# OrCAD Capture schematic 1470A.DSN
size Custom
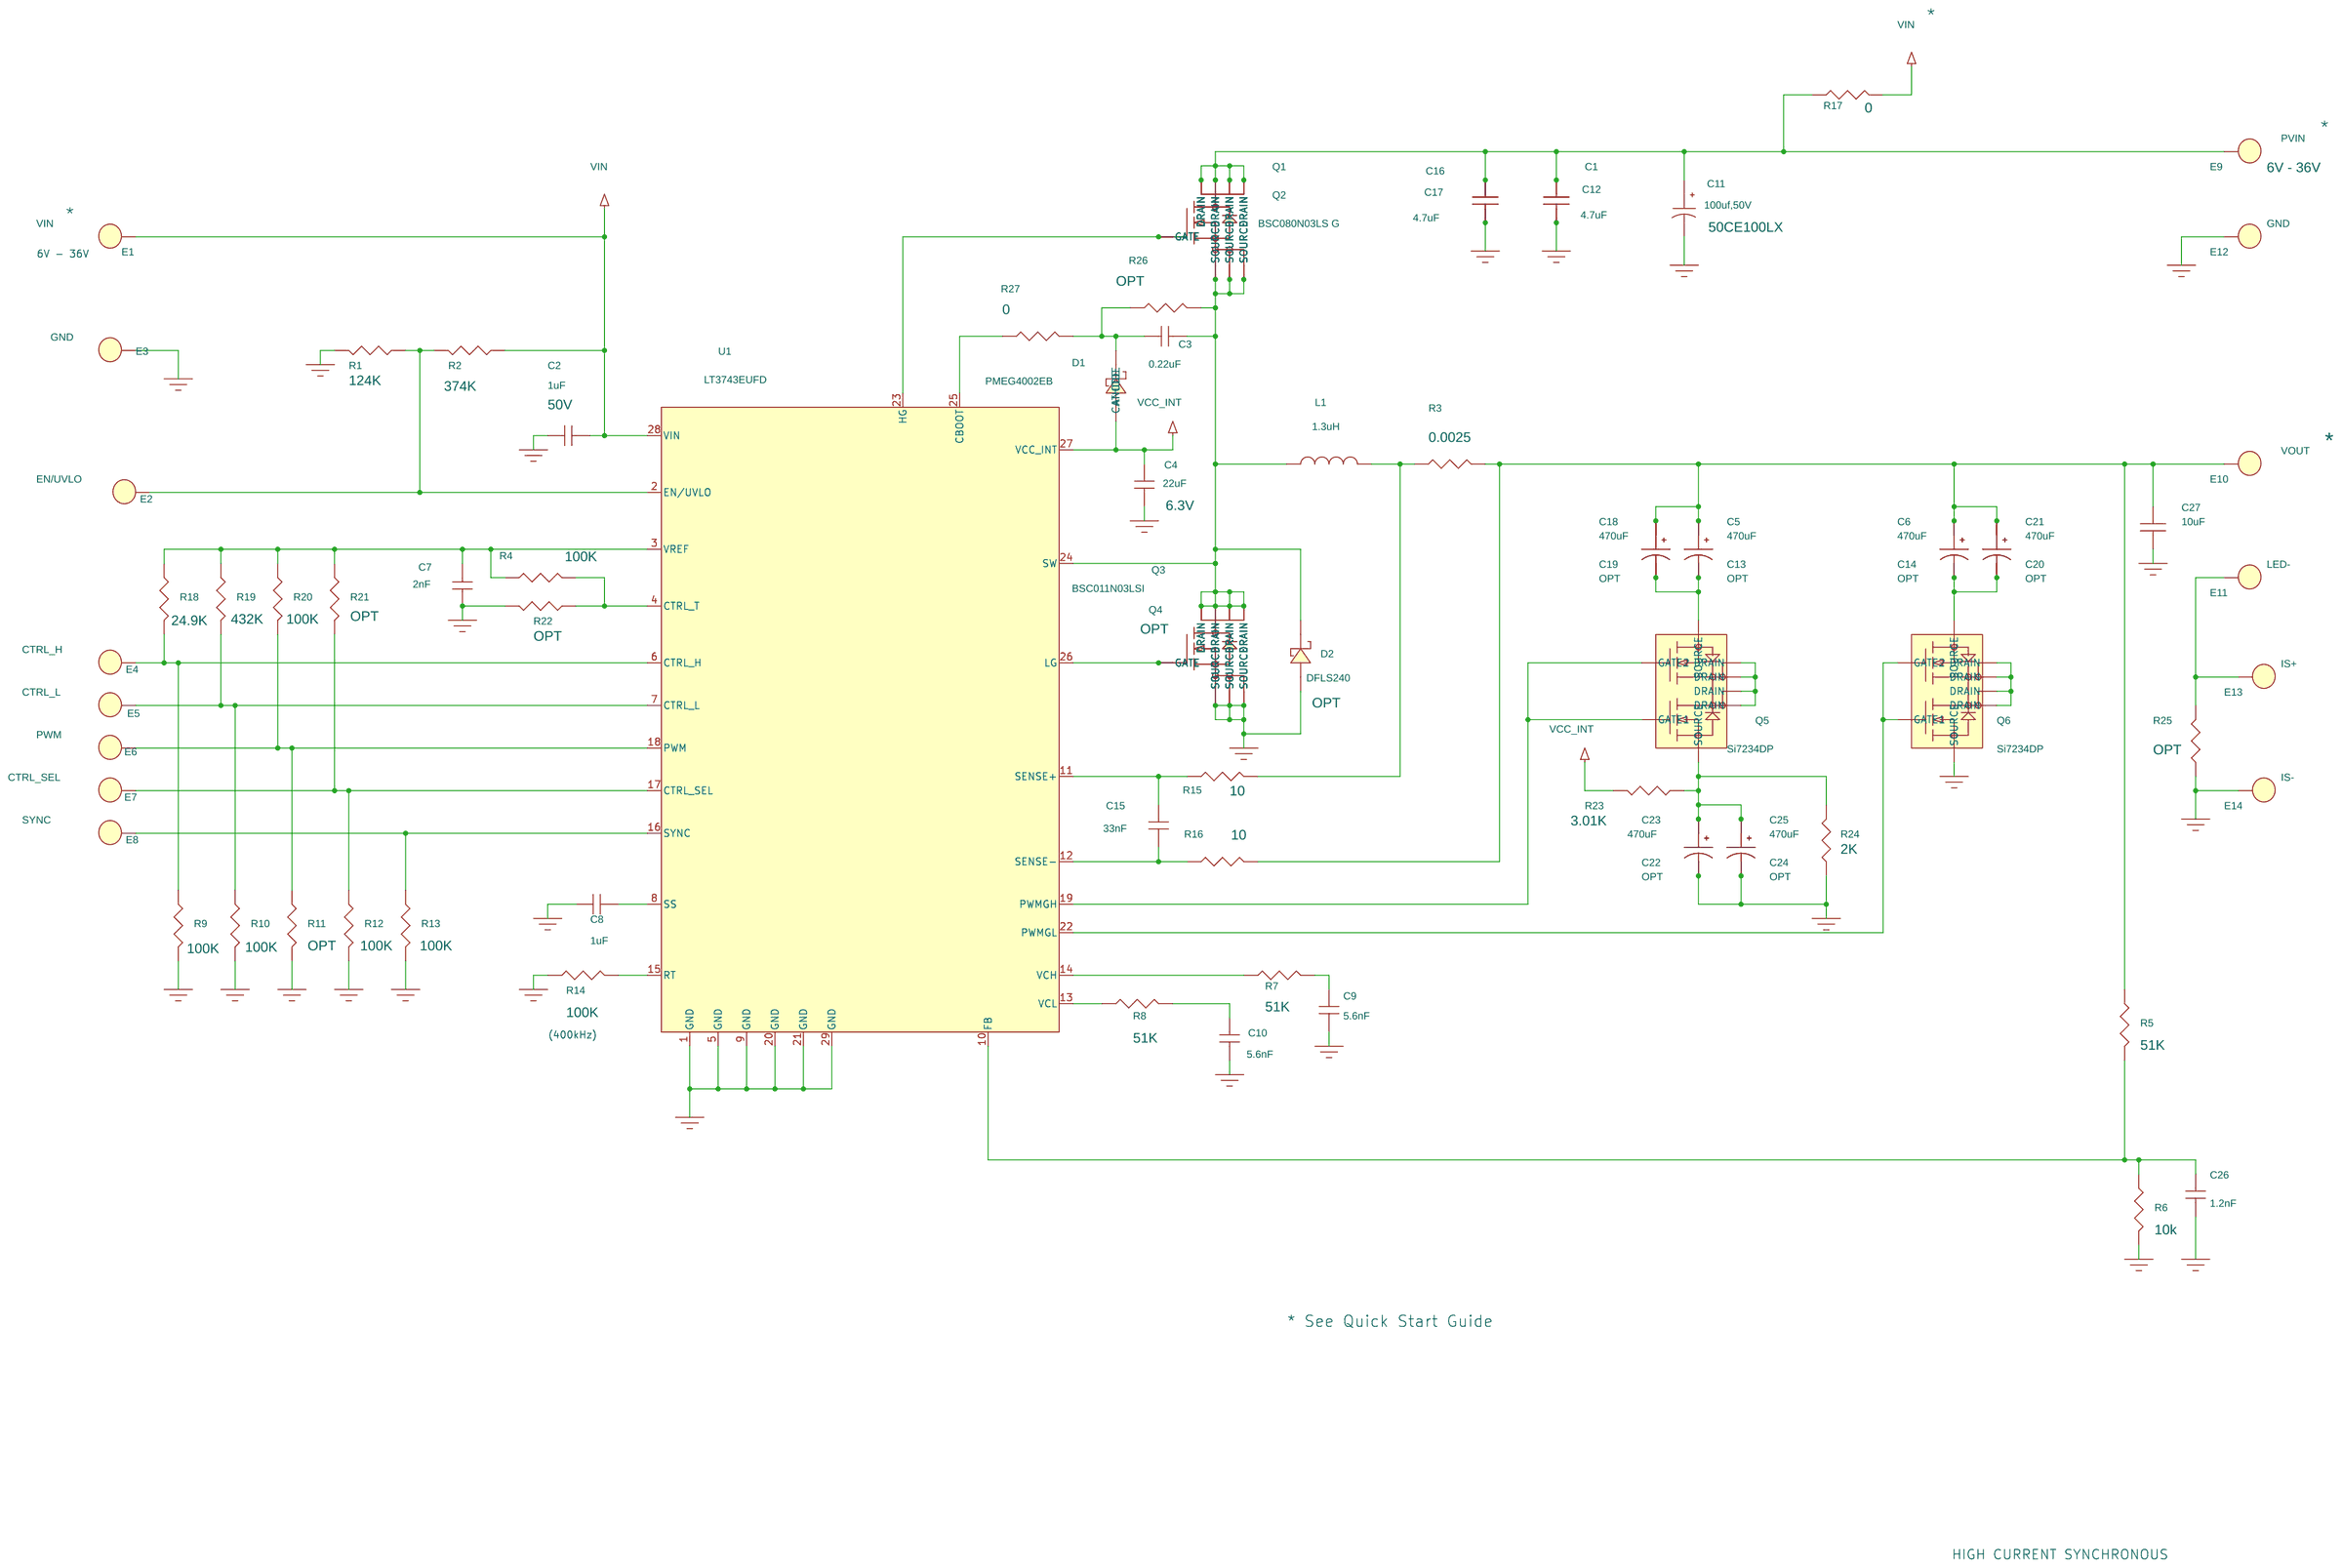
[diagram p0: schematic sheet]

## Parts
C1  4.7uF  [1210]
C2  1uF  [0805]
C3  0.22uF  [0603]
C4  22uF  [0805]
C5  470uF  [sanyo-d4d/1210]
C6  470uF  [sanyo-d4d/1210]
C7  2nF  [0603]
C8  1uF  [0603]
C9  5.6nF  [0603]
C10  5.6nF  [0603]
C11  100uf,50V  [SANYO\8X10]
C12  4.7uF  [1210]
C13  OPT  [sanyo-d4d/1210]
C14  OPT  [sanyo-d4d/1210]
C15  33nF  [0603]
C16  4.7uF  [1210]
C17  4.7uF  [1210]
C18  470uF  [sanyo-d4d/1210]
C19  OPT  [sanyo-d4d/1210]
C20  OPT  [sanyo-d4d/1210]
C21  470uF  [sanyo-d4d/1210]
C22  OPT  [sanyo-d4d/1210]
C23  470uF  [sanyo-d4d/1210]
C24  OPT  [sanyo-d4d/1210]
C25  470uF  [sanyo-d4d/1210]
C26  1.2nF  [0603]
C27  10uF  [1206]
D1  PMEG4002EB  [SOD523]
D2  DFLS240  [DI123]
E1  TURRETS  [MILLMAX-2501-2]
E2  TURRETS  [MILLMAX-2501-2]
E3  TURRETS  [MILLMAX-2501-2]
E4  TURRETS  [MILLMAX-2501-2]
E5  TURRETS  [MILLMAX-2501-2]
E6  TURRETS  [MILLMAX-2501-2]
E7  TURRETS  [MILLMAX-2501-2]
E8  TURRETS  [MILLMAX-2501-2]
E9  TURRETS  [KEY-575-4]
E10  TURRETS  [KEY-575-4]
E11  TURRETS  [KEY-575-4]
E12  TURRETS  [KEY-575-4]
E13  TURRETS  [MILLMAX-2501-2]
E14  TURRETS  [MILLMAX-2501-2]
L1  1.3uH  [IND-IHLP-4040-5050]
Q1  BSC080N03LS G  [LFPAK/SO]
Q2  BSC080N03LS G  [LFPAK/SO]
Q3  BSC011N03LSI  [LFPAK/SO]
Q4  OPT  [LFPAK/SO]
Q5  Si7234DP  [LFPAK/SO]
Q6  Si7234DP  [LFPAK/SO]
R1  124K  [0603]
R2  374K  [0603]
R3  0.0025  [2512]
R4  100K  [0603]
R5  51K  [0603]
R6  10k  [0603]
R7  51K  [0603]
R8  51K  [0603]
R9  100K  [0603]
R10  100K  [0603]
R11  OPT  [0603]
R12  100K  [0603]
R13  100K  [0603]
R14  100K  [0603]
R15  10  [0603]
R16  10  [0603]
R17  0  [0603]
R18  24.9K  [0603]
R19  432K  [0603]
R20  100K  [0603]
R21  OPT  [0603]
R22  OPT  [0603]
R23  3.01K  [0603]
R24  2K  [0603]
R25  OPT  [2512]
R26  OPT  [0603]
R27  0  [0603]
U1  LT3743EUFD  [QFN28PIN-4X5]

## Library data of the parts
C1 C12 C16 C17 = EMK212BJ475MG: 1st Part Field: 50V
C2 = 06033C104KAT2A: 1st Part Field: 50V
C3 C7-C10 C15 C26 = 06033C104KAT2A
C4 = 06033C104KAT2A: 1st Part Field: 6.3V
C5 C6 C13 C14 C18-C25 = CAPACITOR_POL
C11 = 4TPE220MF: 1st Part Field: 2.5V; 4th Part Field: 50CE100LX; 5th Part Field: 2R5TPE330M9
C27 = EMK212BJ475MG: 1st Part Field: 25V
D1 = DIODE_SCHOTTKY_1
D2 = DIODE_SCHOTTKY: 1 R: OPT
E1 = TURRETS_1: Label: VIN; Manufacturer P/N: 2308-2; Vendor: Digikey; Vendor P/N: 2308-2
E2 = TURRETS_1: Label: EN/UVLO; Manufacturer P/N: 2308-2; Vendor: Digikey; Vendor P/N: 2308-2
E3 E12 = TURRETS_1: Label: GND; Manufacturer P/N: 2308-2; Vendor: Digikey; Vendor P/N: 2308-2
E4 = TURRETS_1: Label: CTRL_H; Manufacturer P/N: 2308-2; Vendor: Digikey; Vendor P/N: 2308-2
E5 = TURRETS_1: Label: CTRL_L; Manufacturer P/N: 2308-2; Vendor: Digikey; Vendor P/N: 2308-2
E6 = TURRETS_1: Label: PWM; Manufacturer P/N: 2308-2; Vendor: Digikey; Vendor P/N: 2308-2
E7 = TURRETS_1: Label: CTRL_SEL; Manufacturer P/N: 2308-2; Vendor: Digikey; Vendor P/N: 2308-2
E8 = TURRETS_1: Label: SYNC; Manufacturer P/N: 2308-2; Vendor: Digikey; Vendor P/N: 2308-2
E9 = TURRETS_1: Label: PVIN; Manufacturer P/N: 2308-2; Vendor: Digikey; Vendor P/N: 2308-2; Volts/Watts: 6V - 36V
E10 = TURRETS_1: Label: VOUT; Manufacturer P/N: 2308-2; Vendor: Digikey; Vendor P/N: 5V Clamp; Volts/Watts: *
E11 = TURRETS_1: Label: LED-; Manufacturer P/N: 2308-2; Vendor: Digikey; Vendor P/N: 2308-2
E13 = TURRETS_1: Label: IS+; Manufacturer P/N: 2308-2; Vendor: Digikey; Vendor P/N: 2308-2
E14 = TURRETS_1: Label: IS-; Manufacturer P/N: 2308-2; Vendor: Digikey; Vendor P/N: 2308-2
L1 = INDUCTOR
Q1-Q4 = 2N7000_4
Q5 Q6 = 2N7000_3
R1-R27 = CJ06-000M
U1 = LT3743EUF_25

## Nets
GND: C1.2 C2.1 C4.2 C7.1 C8.1 C9.2 C10.2 C11.2 C12.2 C16.2 C17.2 C22.2 C23.2 C24.2 C25.2 C26.2 C27.2 D2.1(ANODE) E3.1(TP) E12.1(TP) E14.1(TP) Q3.1(SOURCE) Q3.2(SOURCE) Q3.3(SOURCE) Q4.1(SOURCE) Q4.2(SOURCE) Q4.3(SOURCE) Q6.3(SOURCE) R1.1 R6.1 R9.1 R10.1 R11.1 R12.1 R13.1 R14.2 R22.1 R24.2 R25.2 U1.1(GND) U1.5(GND) U1.9(GND) U1.20(GND) U1.21(GND) U1.29(GND)
VCC_INT: C4.1 D1.1(ANODE) R23.1 U1.27(VCC_INT)
VIN: C2.2 E1.1(TP) R2.2 R17.1 U1.28(VIN)
N17675432: E2.1(TP) R1.2 R2.1 U1.2(EN/UVLO)
N17680723: E4.1(TP) R9.2 R18.1 U1.6(CTRL_H)
N17680759: E5.1(TP) R10.2 R19.1 U1.7(CTRL_L)
N17680841: E8.1(TP) R13.2 U1.16(SYNC)
N17681921: E7.1(TP) R12.2 R21.1 U1.17(CTRL_SEL)
N17682572: E6.1(TP) R11.2 R20.1 U1.18(PWM)
N17684664: Q1.4(GATE) Q2.4(GATE) U1.23(HG)
N17686510: C1.1 C11.1 C12.1 C16.1 C17.1 E9.1(TP) Q1.5(DRAIN) Q1.6(DRAIN) Q1.7(DRAIN) Q1.8(DRAIN) Q2.5(DRAIN) Q2.6(DRAIN) Q2.7(DRAIN) Q2.8(DRAIN) R17.2
N17686596: C3.2 D2.2(CATHODE) L1.1 Q1.1(SOURCE) Q1.2(SOURCE) Q1.3(SOURCE) Q2.1(SOURCE) Q2.2(SOURCE) Q2.3(SOURCE) Q3.5(DRAIN) Q3.6(DRAIN) Q3.7(DRAIN) Q3.8(DRAIN) Q4.5(DRAIN) Q4.6(DRAIN) Q4.7(DRAIN) Q4.8(DRAIN) R26.1 U1.24(SW)
N17690478: L1.2 R3.2 R15.1
N17690492: C5.1 C6.1 C13.1 C14.1 C18.1 C19.1 C20.1 C21.1 C27.1 E10.1(TP) R3.1 R5.2 R16.1
N17691071: C15.1 R15.2 U1.11(SENSE+)
N17691505: C15.2 R16.2 U1.12(SENSE-)
N17691929: Q5.2(GATE2) Q5.4(GATE1) U1.19(PWMGH)
N17692031: Q6.2(GATE2) Q6.4(GATE1) U1.22(PWMGL)
N17693878: C26.1 R5.1 R6.2 U1.10(FB)
N17693966: R7.2 U1.14(VCH)
N17694003: R8.2 U1.13(VCL)
N17694097: C9.1 R7.1
N17694111: C10.1 R8.1
N17698032: R4.1 R22.2 U1.4(CTRL_T)
N17698069: C7.2 R4.2 R18.2 R19.2 R20.2 R21.2 U1.3(VREF)
N17699197: R14.1 U1.15(RT)
N17704639: R27.2 U1.25(CBOOT)
N17713063: C8.2 U1.8(SS)
N17719496: Q3.4(GATE) Q4.4(GATE) U1.26(LG)
N17721353: Q5.5(DRAIN) Q5.6(DRAIN) Q5.7(DRAIN) Q5.8(DRAIN)
N17721800: Q6.5(DRAIN) Q6.6(DRAIN) Q6.7(DRAIN) Q6.8(DRAIN)
N17726034: E11.1(TP) E13.1(TP) R25.1
N17737817: C22.1 C23.1 C24.1 C25.1 Q5.3(SOURCE) R23.2 R24.1
N17754117: C5.2 C13.2 C18.2 C19.2 Q5.1(SOURCE)
N17754465: C6.2 C14.2 C20.2 C21.2 Q6.1(SOURCE)
N17759565: C3.1 D1.2(CATHODE) R26.2 R27.1

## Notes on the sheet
- *
- *
- *
- 6V - 36V
- (400kHz)
- * See Quick Start Guide
- HIGH CURRENT SYNCHRONOUS
